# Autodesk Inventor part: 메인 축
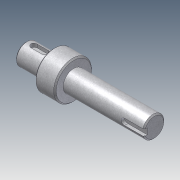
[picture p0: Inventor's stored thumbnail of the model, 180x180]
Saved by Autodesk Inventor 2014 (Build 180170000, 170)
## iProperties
Company: 한국ATC센터
Created: 2014-10
Part Number: 메인 축
Document SubType Name: Modeling
Designer: KYOUNG IL JANG
Density: 7.85 g/cm^3
Mass: 229.947 g
Surface Area: 74.3518 cm^2
Volume: 29.2926 cm^3
Material: 강철
Appearance: 금속-강(스테인리스, 브러시됨)
Author: KYOUNG IL JANG
Revision Number: 1
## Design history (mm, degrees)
sketch "스케치1"
  geometry: L1 (10.497, -57.5)-(112.497, -57.5); L2 (10.497, -66)-(32.497, -66); L3 (32.497, -72.5)-(46.5, -72.5); L4 (46.5, -66)-(112.497, -66); L5 (112.497, -66)-(112.497, -57.5); L6 (10.497, -66)-(10.497, -57.5); L7 (46.5, -69.749)-(46.5, -45.251) reference; L8 (46.5, -72.5)-(46.5, -66); L9 (32.497, -72.5)-(32.497, -66); L10 (32.497, -35)-(32.497, -80) reference; 3 further points
  constraints: 16 end point, 3 point on line, 2 parallel, 2 perpendicular, 1 collinear, 1 horizontal, 1 midpoint
  dimensions: "d0" = 17 diameter of L4 L1; "d1" = 30 diameter of L3 L1; "d2" = 22 distance of L2.start L2.end; "d3" = 65.99692 distance of L4.start L4.end (derived); "d5" = 17 diameter of L2 L1; "d19" = 80 distance between parallel lines of L5 L9
revolve "회전1" sketch "스케치1" stored, may be unused: angle "d4" = 90 deg
chamfer "모따기1" distance "d6" = 1; stored, may be unused: second distance "d7" = 2, angle "d8" = 45 deg
node "작업 평면1"
sketch "스케치2"
  geometry: L1 (-11, -7.5)-(-11, 7.5) reference; L2 (-4.5, 2.5)-(4.5, 2.5); L3 (4.5, -2.5)-(-4.5, -2.5); A1 r 2.5 centre (4.5, 0) between (4.5, -2.5) and (4.5, 2.5); A2 r 2.5 centre (-4.5, 0) between (-4.5, 2.5) and (-4.5, -2.5); 2 further points
  constraints: 4 end point, 4 point on circle, 4 tangent, 2 centre point, 1 horizontal alignment, 1 midpoint, 1 parallel, 1 perpendicular
  dimensions: "d9" = 5 distance between parallel lines of L3 L2; "d10" = 14 dimension on A1 A2; "d11" = 4 distance edge to line of A2 L1
extrude "돌출1" cut sketch "스케치2" distance "d12" = 3; taper "d13" = 0 deg
node "작업 평면2"
sketch "스케치3"
  geometry: L1 (32.998, 7.5)-(32.998, -7.5) reference; L2 (32.998, 2.5)-(17.498, 2.5); L3 (17.498, -2.5)-(32.998, -2.5); A1 r 2.5 centre (17.498, 0) between (17.498, 2.5) and (17.498, -2.5); 2 further points
  constraints: 4 end point, 2 perpendicular, 2 point on circle, 2 point on line, 2 tangent, 1 centre point, 1 horizontal alignment, 1 midpoint
  dimensions: "d14" = 5 distance between parallel lines of L3 L2; "d15" = 18 dimension on A1 L1
extrude "돌출2" cut sketch "스케치3" distance "d16" = 3; taper "d17" = 0 deg
node "솔리드1"
node "참조4"
node "참조5"
